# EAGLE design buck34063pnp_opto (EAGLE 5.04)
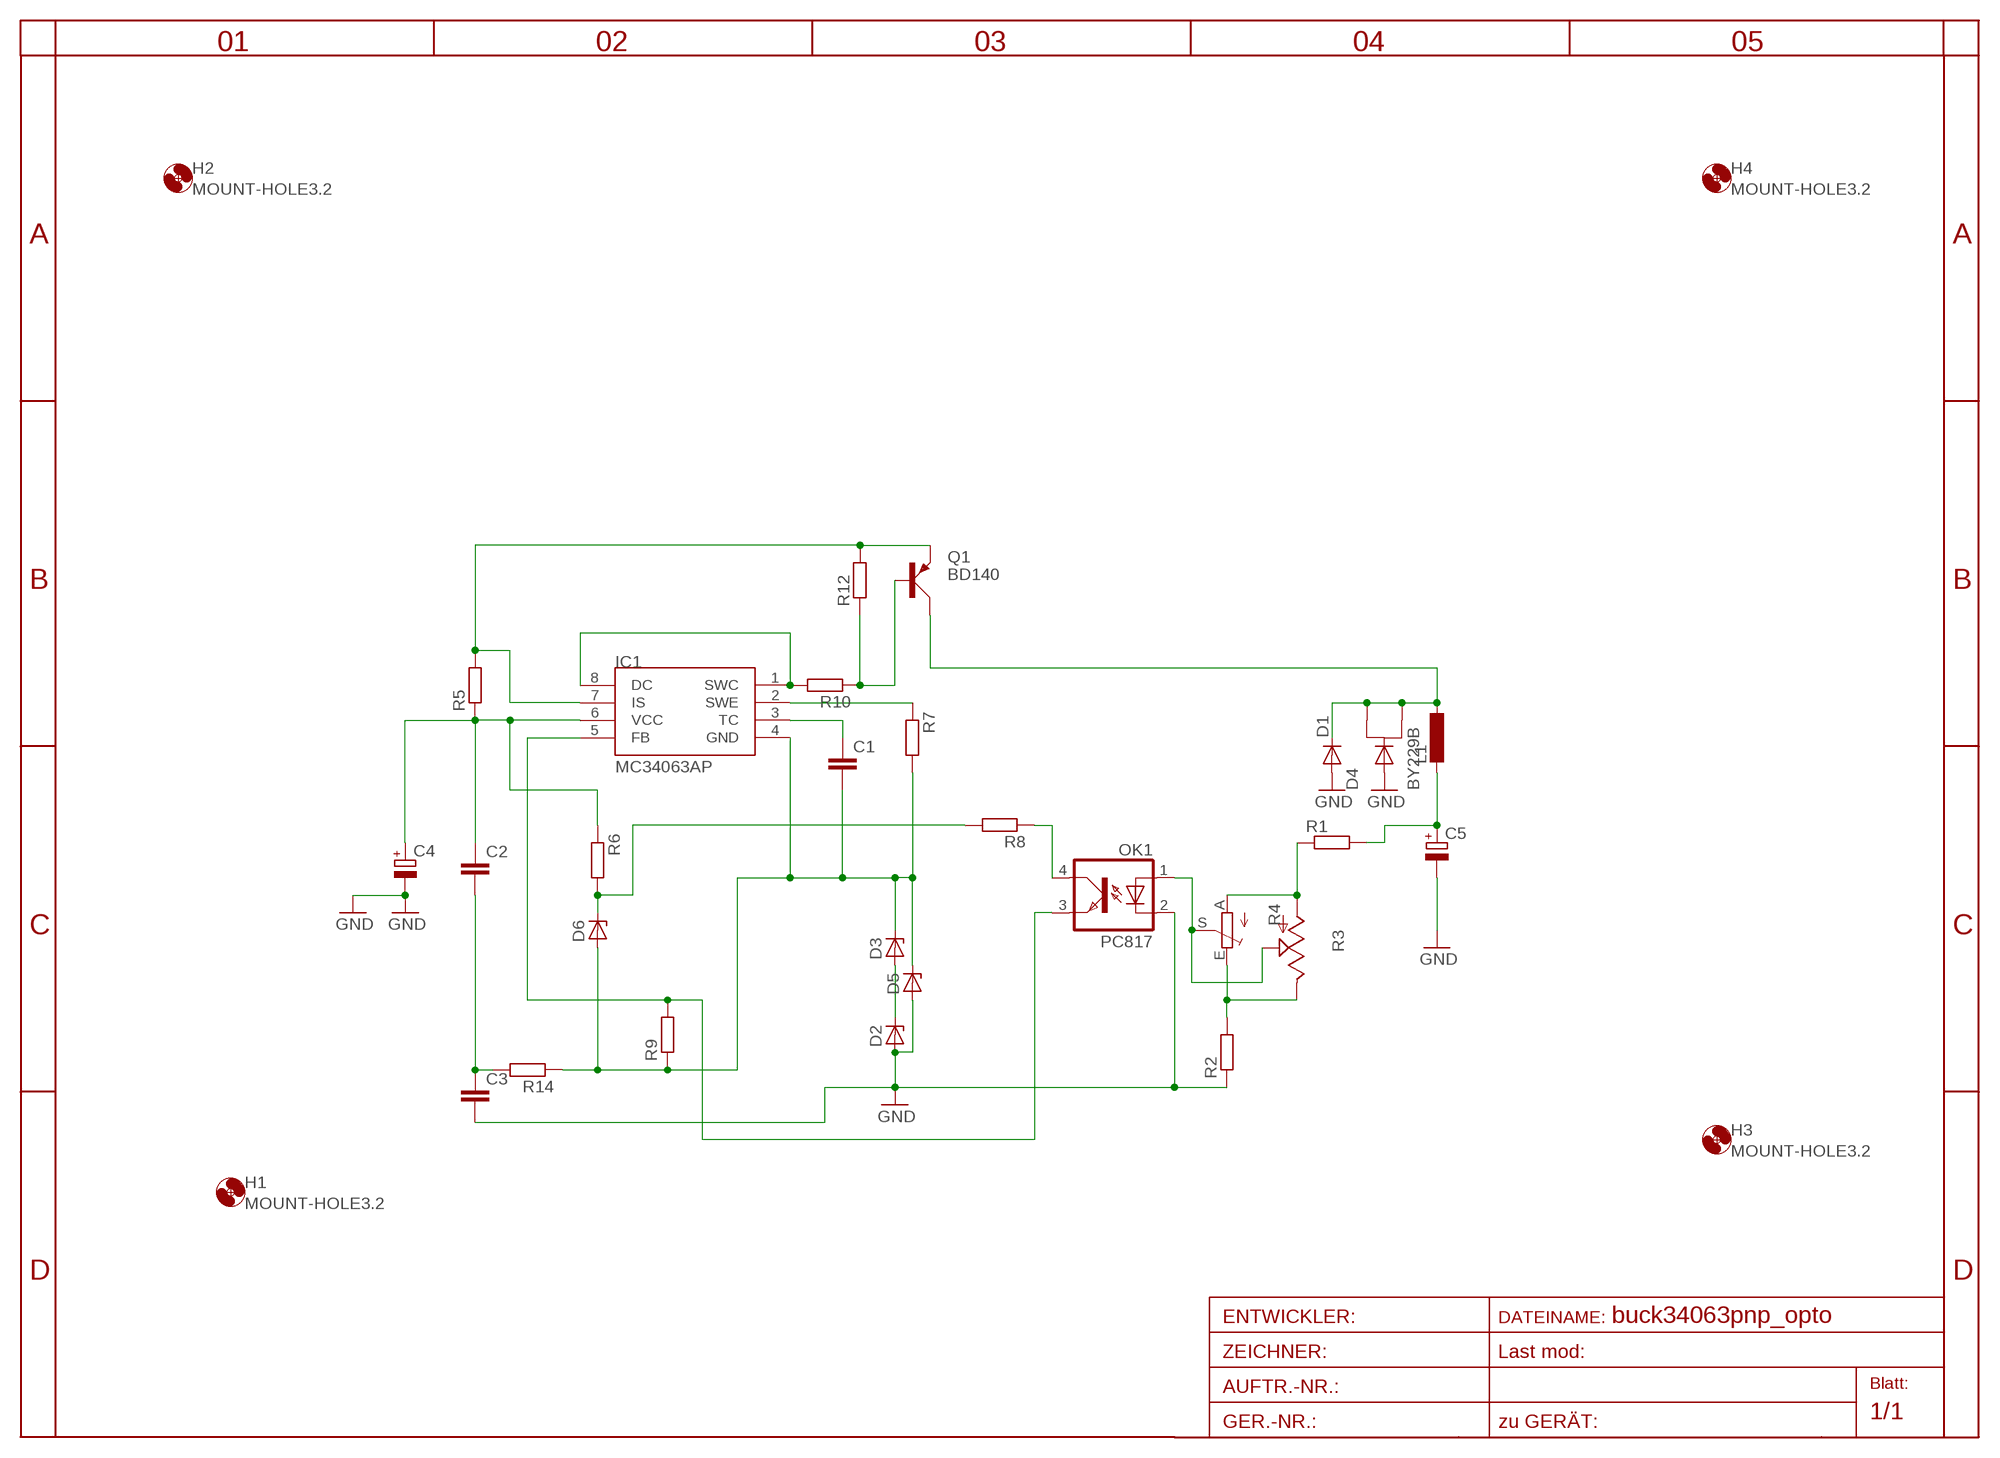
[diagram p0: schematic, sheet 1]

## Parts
C1  C-EU025_050-055X075  [C025_050-055X075]
C2  C-EU025_050-055X075  [C025_050-055X075]
C3  C-EU025_050-055X075  [C025_050-055X075]
C4  CPOL-EUE5-10.5  [E5-10,5]
C5  CPOL-EUE5-10.5  [E5-10,5]
D1  DIODE-DO35-10  [DO35-10]
D2  ZENER-DIODEZD-10  [ZDIO-10]
D3  ZENER-DIODEZD-10  [ZDIO-10]
D4  BY229B  [TO263AB]
D5  ZENER-DIODESMB  [SMB]
D6  ZENER-DIODEZD-10  [ZDIO-10]
H1  MOUNT-HOLE3.2  [3,2]
H2  MOUNT-HOLE3.2  [3,2]
H3  MOUNT-HOLE3.2  [3,2]
H4  MOUNT-HOLE3.2  [3,2]
IC1  MC34063AP  [DIL08]
L1  L-EU0207/10  [0207/10]
OK1  PC817  [DIL04]
Q1  BD140  [TO126AV]
R1  R-EU_0207/10  [0207/10]
R2  R-EU_0207/10  [0207/10]
R3  TRIM_US-CA6V  [CA6V]
R4  TRIM_EU-CA9V  [CA9V]
R5  R-EU_0207/10  [0207/10]
R6  R-EU_0207/10  [0207/10]
R7  R-EU_R0603  [R0603]
R8  R-EU_0207/10  [0207/10]
R9  R-EU_0207/10  [0207/10]
R10  R-EU_0204/7  [0204/7]
R12  R-EU_0207/10  [0207/10]
R14  R-EU_0207/10  [0207/10]

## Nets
DC: IC1.1(SWC) IC1.8(DC) R10.2
E: IC1.7(IS) Q1.E R5.2 R12.2
FB: OK1.1(A) R3.S R4.S
GND: C3.2 C4.- C5.- D1.A D2.A D4.2 D5.A OK1.2(C) R2.1
N$1: R1.1 R3.A R4.A
N$2: Q1.B R10.1 R12.1
N$3: IC1.5(FB) OK1.3(EMIT) R9.2
N$4: D6.C R6.2 R8.2
N$5: D1.C D4.1 D4.K L1.1 Q1.C
N$6: C2.2 C3.1 R14.2
N$8: R2.2 R3.E R4.E
N$11: OK1.4(COL) R8.1
SWE: IC1.2(SWE) R7.1
TC: C1.1 IC1.3(TC)
VCC: C2.1 C4.+ IC1.6(VCC) R5.1 R6.1
VIRTGND: C1.2 D3.C D5.C D6.A IC1.4(GND) R7.2 R9.1 R14.1
VOUT: C5.+ L1.2 R1.2
ZZ: D2.C D3.A

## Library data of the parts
C1-C3 = rcl:C-EU: CAPACITOR, European symbol
C4 C5 = rcl:CPOL-EU: POLARIZED CAPACITOR, European symbol
D1 = diode:DIODE-: DIODE
D2 D3 D5 D6 = diode:ZENER-DIODE: Z-Diode
D4 = diode:BY229B: DIODE Fast Switching Rectifier, 8A (Vishay)
H1-H4 = holes:MOUNT-HOLE: MOUNTING HOLE with drill center marker
IC1 = mc34063:MC34063
L1 = rcl:L-EU: INDUCTOR, European symbol
OK1 = optocoupler:PC817: SHARP OPTO COUPLER
Q1 = transistor-power:BD140: PNP TRANSISTOR
R1 R2 R5-R10 R12 R14 = rcl:R-EU_: RESISTOR, European symbol
R3 = pot:TRIM_US-: POTENTIOMETER
R4 = pot:TRIM_EU-: POTENTIOMETER

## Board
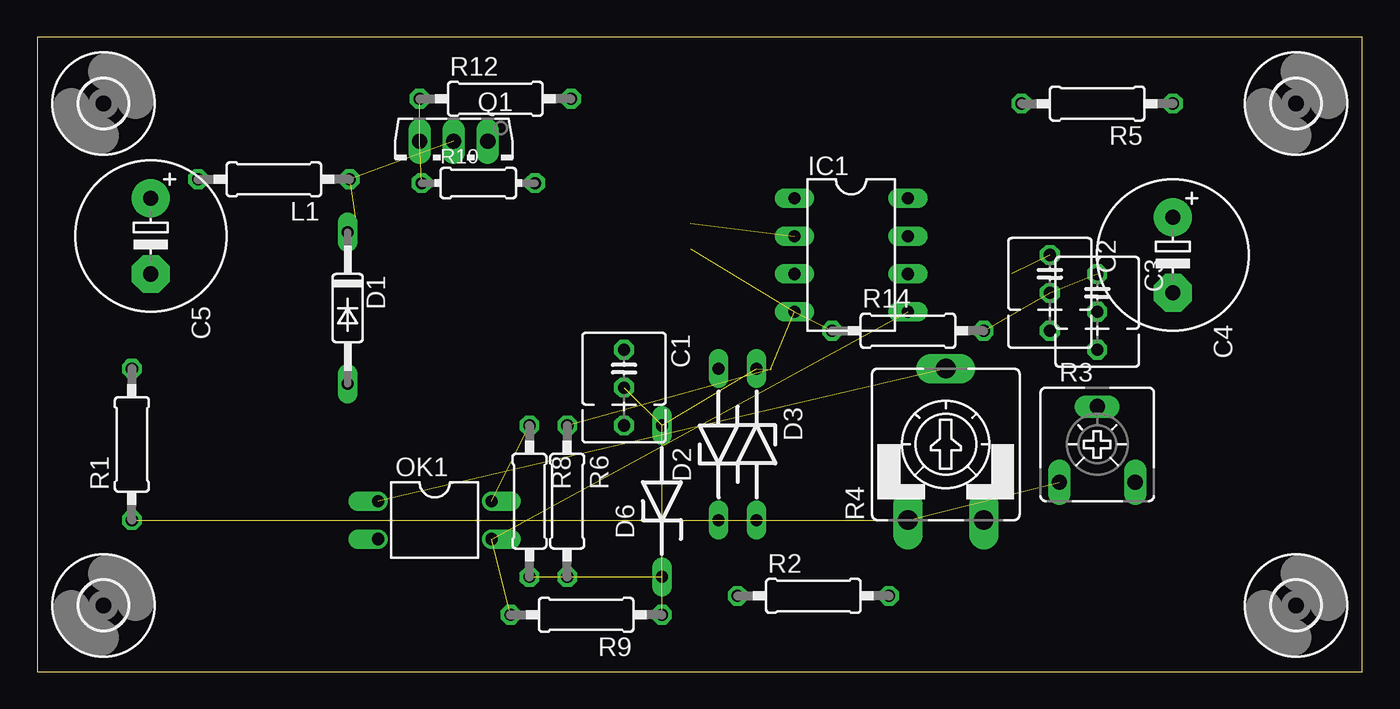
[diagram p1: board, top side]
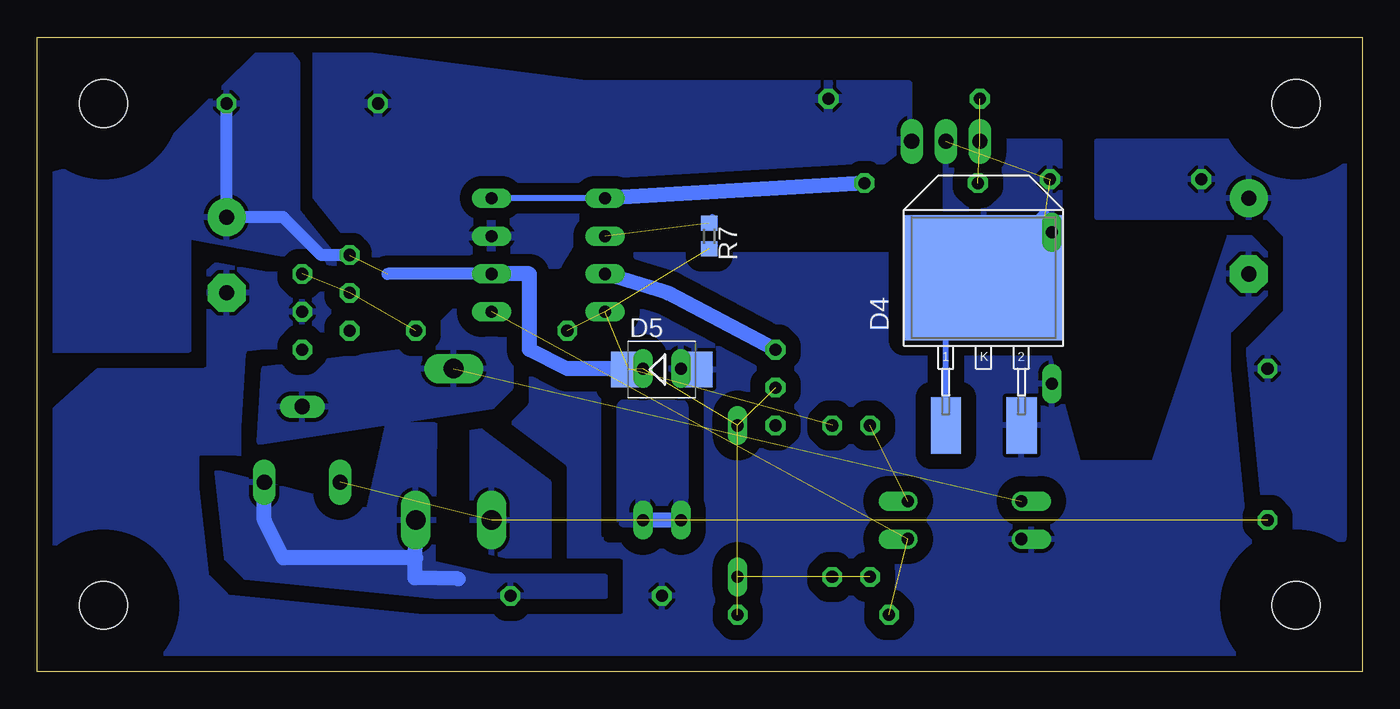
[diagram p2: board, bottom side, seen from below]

Size 88.9 x 42.55 mm. Coordinates in mm from the lower left corner, seen from the top.
Outline: 0,0 88.9,0 88.9,42.55 0,42.55 0,0
Copper layers (1*16): Top 0.035mm / dielectric 1.5mm / Bottom 0.035mm
Design rules "default": minimum track width 10mil, minimum drill 24mil, track to track 8mil, track to pad 8mil, pad to pad 8mil, via to via 8mil, smd to smd 8mil, copper to edge 40mil, drill to drill 8mil, minimum pad ring 10mil, minimum via ring 8mil, stop-mask expansion 4mil, vias tented up to drill 0mil, thermal gap 10mil

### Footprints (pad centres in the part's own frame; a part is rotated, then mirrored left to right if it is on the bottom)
C025_050-055X075 = drill 0.813 octagon: 1 -1.27,0; 2 1.27,0; 3 3.81,0
E5-10,5 = drill 1.016 pad 2.54 round: + -2.54,0 | drill 1.016 pad 2.54 octagon: - 2.54,0
DO35-10 = drill 0.813 long: A 5.08,0; C -5.08,0
ZDIO-10 = drill 0.813 long: A 5.08,0; C -5.08,0
TO263AB = smd 2.032 x 3.81: 1 -2.54,0; 2 2.54,0 | smd 10.668 x 8.382: K 0,9.906
SMB = smd 2.4 x 2.4: A 2.2,0; C -2.2,0
3,2 = hole 3.2: 0,0
DIL08 = drill 0.813 long: 1 -3.81,-3.81; 2 -1.27,-3.81; 3 1.27,-3.81; 4 3.81,-3.81; 5 3.81,3.81; 6 1.27,3.81; 7 -1.27,3.81; 8 -3.81,3.81
0207/10 = drill 0.813 octagon: 1 -5.08,0; 2 5.08,0
DIL04 = drill 0.813 offset: 1 -1.27,-3.81; 2 1.27,-3.81; 3 1.27,3.81; 4 -1.27,3.81
TO126AV = drill 1.016 long: B 2.286,-1.27; C 0,-1.27; E -2.286,-1.27
CA6V = drill 1.016 long: A -2.54,-2.54; E 2.54,-2.54; S 0,2.54
CA9V = drill 1.321 long: A -2.54,-5.08; E 2.54,-5.08; S 0,5.08
R0603 = smd 1 x 1.1: 1 -0.85,0; 2 0.85,0
0204/7 = drill 0.813 octagon: 1 -3.81,0; 2 3.81,0

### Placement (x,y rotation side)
C1  39.37,20.32 270 top
C2  67.94,26.67 270 top
C3  71.12,25.4 270 top
C4  76.2,27.94 270 top
C5  7.62,29.21 270 top
D1  20.83,24.38 270 top
D2  45.72,15.24 90 top
D3  48.26,15.24 270 top
D4  25.4,16.51 0 bottom
D5  46.99,20.26 0 bottom
D6  41.91,11.43 90 top
H1  84.45,38.1 0 top
H2  84.45,4.45 0 top
H3  4.45,4.45 0 top
H4  4.45,38.1 0 top
IC1  54.61,27.94 270 top
L1  15.88,33.02 180 top
OK1  26.67,10.16 270 top
Q1  27.94,34.29 180 top
R1  6.35,15.24 90 top
R2  52.07,5.08 0 top
R3  71.12,15.24 0 top
R4  60.96,15.24 0 top
R5  71.12,38.1 180 top
R6  35.56,11.43 270 top
R7  43.81,29.21 270 bottom
R8  33.02,11.43 270 top
R9  36.83,3.81 180 top
R10  29.59,32.77 0 top
R12  30.73,38.42 0 top
R14  58.42,22.86 0 top

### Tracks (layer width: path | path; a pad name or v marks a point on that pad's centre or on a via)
DC
  Bottom 0.406: IC1.1 IC1.8
  Bottom 1.016: R10.2 IC1.1
E
  pour Bottom (isolate 0.813, rank 3): 70.29,41.72 70.48,27.3 53.98,27.3 52.07,30.48 45.72,30.48 44.45,31.75 35.56,31.75 30.48,35.56 30.48,39.37 52.07,39.37
FB  (1 unrouted)
  pour Bottom (isolate 1.016): 57.15,26.67 57.15,19.05 58.42,17.78 73.98,15.37 73.66,20.32 63.5,21.59 59.69,25.4 59.69,26.67
GND
  Bottom 1.016: D2.A 44.85,20.32 D5.A
  pour Bottom (isolate 1.016, rank 5): 1.27,2.54 1.27,24.13 6.35,29.21 8.89,29.21 13.97,13.97 19.05,13.97 22.86,27.94 76.2,27.94 88.9,16.51 88.9,1.27 2.54,1.27
N$1  (2 unrouted)
  pour Bottom (isolate 1.016, rank 2): 54.61,12.7 54.61,7.62 59.69,7.62 59.69,16.51
N$2  (2 unrouted)
N$3  (2 unrouted)
N$4  (2 unrouted)
N$5  (2 unrouted)
  Bottom 0.406: D4.1 27.94,23.88 26.23,25.59 | 26.23,25.59 D4.K | 29.21,26.04 28.57,26.67 27.3,26.67 26.23,25.59
  Bottom 1.016: D1.C 21.34,30.48 D4.K
  pour Bottom (isolate 1.016, rank 4): 20.32,35.56 20.32,30.48 27.94,30.48 27.94,35.56
N$6  (2 unrouted)
N$8
  Bottom 0.406: R4.E 63.5,7.62
  Bottom 1.016: R3.E 73.66,10.16 72.39,7.62 63.5,7.62 | R4.E 63.56,6.29 60.64,6.22
  pour Bottom (isolate 1.016): 62.23,16.51 65.41,16.51 66.67,10.79 76.83,13.34 76.2,7.62 74.93,6.35 62.23,5.08 50.8,5.08 50.8,6.35 58.42,6.35 62.36,7.24
N$11  (1 unrouted)
SWE  (1 unrouted)
  Bottom 0.406: R7.1 43.6,30.48
TC
  Bottom 1.016: C1.1 46.61,25.4 IC1.3
VCC  (2 unrouted)
  Bottom 0.813: R5.1 C4.+ 72.39,30.48 69.85,27.94 C2.1 | IC1.6 65.41,26.67
  Bottom 1.016: IC1.6 55.88,26.67 55.88,21.59 53.34,20.32 49.25,20.32
  pour Bottom (isolate 1.016, rank 2): 73.66,41.85 80.01,35.56 88.9,33.02 88.9,21.59 78.74,21.59 78.74,29.21 68.58,27.3 71.12,30.48 71.44,30.86 71.44,40.83 72.26,41.85
VIRTGND  (7 unrouted)
VOUT
  pour Bottom (isolate 1.016, rank 3): 17.78,35.56 2.54,35.56 0,33.02 0,21.59 1.27,8.89 6.35,8.89 7.62,21.59 5.08,24.13 5.08,29.21 6.35,30.48 17.78,30.48
ZZ
  Bottom 1.016: D2.C D3.A
  pour Bottom (isolate 0.813, rank 3): 45.72,17.78 45.72,10.16 49.53,10.16 49.53,17.78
